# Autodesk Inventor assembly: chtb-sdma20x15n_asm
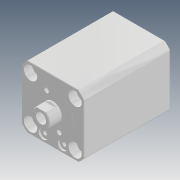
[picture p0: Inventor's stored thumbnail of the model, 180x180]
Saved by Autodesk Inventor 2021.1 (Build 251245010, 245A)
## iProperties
Created: 2018-05
Part Number: chtb-sdma20x15n_asm
Description: STEP AP214
Document SubType Name: Assembly
Designer: user
Title: chtb-sdma20x15n_asm.STEP
Revision Number: ÈÎºÎ
Sending System: SolidWorks 2016
Preprocessor: SwSTEP 2.0
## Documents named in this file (5)
- D:\Vault_2016\Projekty\Clamptek\Hydraulic\CHTB\CHTB-20\Inventor\CHTB-SDMA20x15N\chtb-sdma20x15n_asm.iam
- D:\Vault_2016\Projekty\Clamptek\Hydraulic\CHTB\CHTB-20\Inventor\CHTB-SDMA20x15N\CHTB-SDMA20X15NBT.ipt
- D:\Vault_2016\Projekty\Clamptek\Hydraulic\CHTB\CHTB-20\Inventor\CHTB-SDMA20x15N\CHTB-SDMA20X15NHSG.ipt
- D:\Vault_2016\Projekty\Clamptek\Hydraulic\CHTB\CHTB-20\Inventor\CHTB-SDMA20x15N\QG_3.ipt
- D:\Vault_2016\Projekty\Clamptek\Hydraulic\CHTB\CHTB-20\Inventor\CHTB-SDMA20x15N\socket set screw flat point_iso_ISO 4026 - M5 x 5-N.ipt
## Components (5 placed, 5 different names)
1. CHTB-SDMA20X15NBT_1
2. CHTB-SDMA20X15NHSG_2
3. QG_3_3
4. socket set screw flat point_iso_ISO 4026 - M5 x 5-N_4
5. socket set screw flat point_iso_ISO 4026 - M5 x 5-N_5
